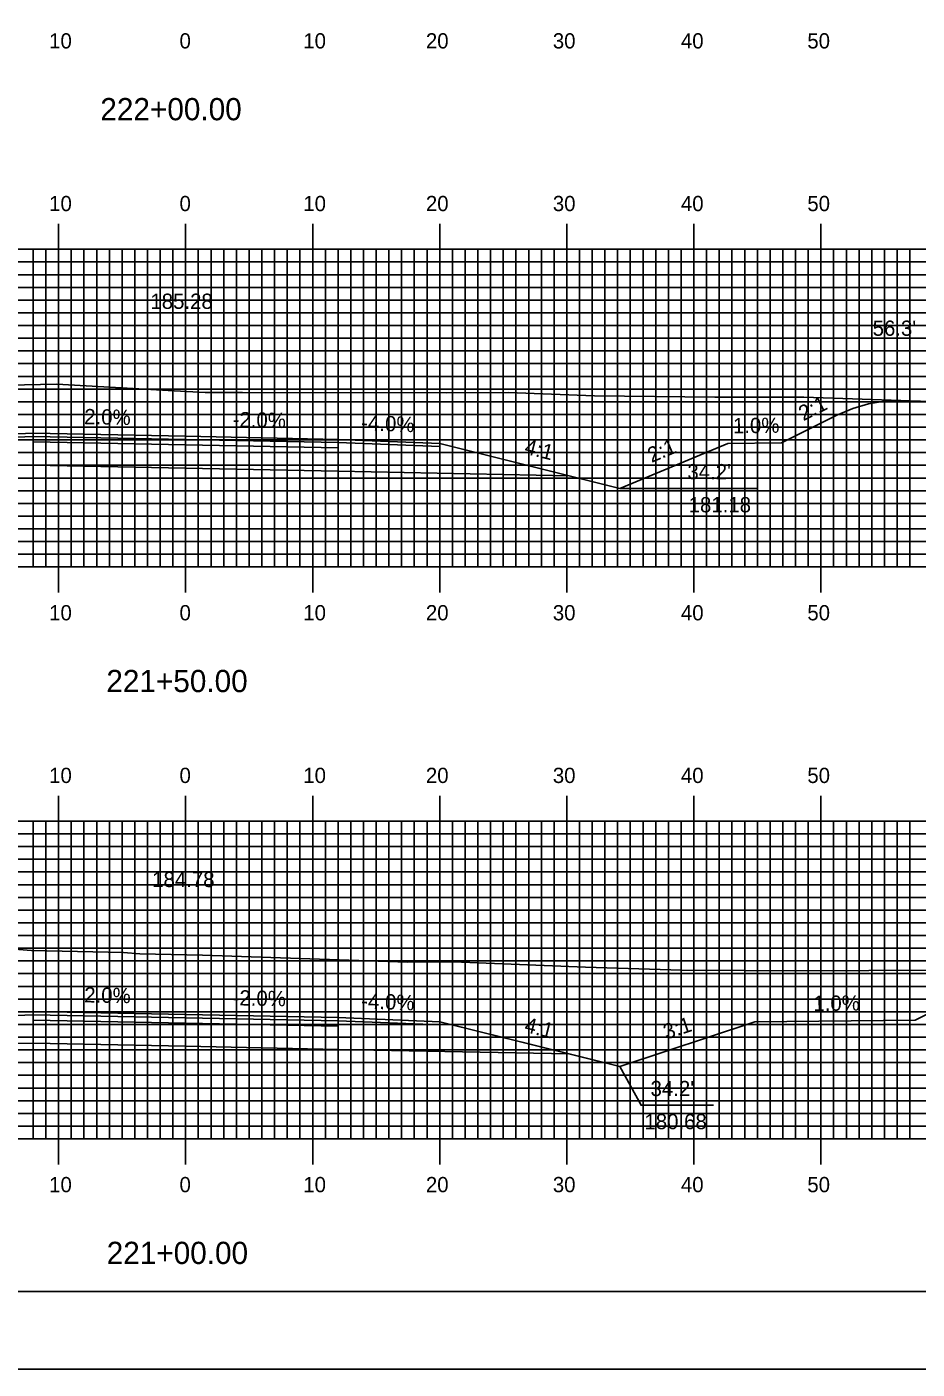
# Model space of a CAD drawing. Extents: x 1797601 to 1797944, y 442591 to 442811.
# Drawn here: x 1797753.9 to 1797824, y 442590.5 to 442696.2 of the extents above; entities that cross this region are included whole.
import ezdxf

# ---------------------------------------------------------------- set-up
doc = ezdxf.new("R2010")
doc.units = 0
for name, color, linetype in [('ANNOTATION', 7, 'Continuous'), ('BORDER', 7, 'Continuous'), ('D_Roadway_Centerline', 7, 'Continuous'), ('D_Roadway_Centerline_Text', 7, 'Continuous'), ('D_Roadway_Edge_Shoulder', 7, 'Continuous'), ('D_Roadway_Edge_TW', 7, 'Continuous'), ('D_Roadway_Pavement', 7, 'Continuous'), ('D_Roadway_SlopeLines', 7, 'Continuous'), ('D_Roadway_SubGrade', 7, 'Continuous'), ('D_Text_Standard', 7, 'Continuous'), ('H_V ANNOTATION', 7, 'Continuous'), ('MAJOR', 7, 'Continuous'), ('MINOR', 7, 'Continuous'), ('PDRAIN', 7, 'Continuous'), ('PLOT BOUNDARY', 7, 'Continuous'), ('S_Roadway_Centerline', 7, 'Continuous')]:
    doc.layers.add(name, color=color, linetype=linetype)

msp = doc.modelspace()

# ---------------------------------------------------------------- linework, layer by layer
at = {"layer": 'ANNOTATION'}
msp.add_lwpolyline([(1797807.99, 442611.31), (1797802.29, 442611.31), (1797800.62, 442614.35)], dxfattribs=at)
at = {"layer": 'BORDER'}
msp.add_lwpolyline([(1797616.84, 442596.67), (1797936.84, 442596.67), (1797936.84, 442806.67), (1797616.84, 442806.67)], close=True, dxfattribs=at)
at = {"layer": 'D_Roadway_Centerline'}
for points in [[(1797710.19, 442668.6), (1797711.44, 442668.5), (1797712.69, 442668.24), (1797713.94, 442667.84), (1797715.19, 442667.28), (1797721.99, 442663.89), (1797723.77, 442663.87), (1797732.27, 442660.33), (1797736.27, 442661.33), (1797746.44, 442663.87), (1797754.44, 442664.19), (1797766.44, 442663.95), (1797778.44, 442663.71), (1797786.44, 442663.39), (1797796.62, 442660.85), (1797800.62, 442659.85), (1797809.12, 442663.39), (1797813.34, 442663.43), (1797817.69, 442665.61), (1797818.94, 442666.15), (1797820.19, 442666.52), (1797821.44, 442666.73), (1797822.69, 442666.77)], [(1797698.94, 442623.65), (1797700.19, 442623.55), (1797701.44, 442623.31), (1797702.69, 442622.91), (1797703.94, 442622.36), (1797711.73, 442618.47), (1797721.64, 442618.37), (1797732.27, 442614.83), (1797736.27, 442615.83), (1797746.44, 442618.37), (1797754.44, 442618.69), (1797766.44, 442618.45), (1797778.44, 442618.21), (1797786.44, 442617.89), (1797796.62, 442615.35), (1797800.62, 442614.35), (1797811.25, 442617.89), (1797823.86, 442618.01), (1797828.94, 442620.56), (1797830.19, 442621.1), (1797831.44, 442621.48), (1797832.69, 442621.7), (1797833.94, 442621.75)]]:
    msp.add_lwpolyline(points, dxfattribs=at)
at = {"layer": 'D_Roadway_Edge_Shoulder'}
for points in [[(1797754.44, 442664.19), (1797746.44, 442663.87), (1797746.44, 442663.62), (1797754.44, 442663.94)], [(1797778.44, 442663.71), (1797786.44, 442663.39), (1797786.44, 442663.14), (1797778.44, 442663.46)], [(1797754.44, 442618.69), (1797746.44, 442618.37), (1797746.44, 442618.12), (1797754.44, 442618.44)], [(1797778.44, 442618.21), (1797786.44, 442617.89), (1797786.44, 442617.64), (1797778.44, 442617.96)]]:
    msp.add_lwpolyline(points, close=True, dxfattribs=at)
at = {"layer": 'D_Roadway_Edge_TW'}
for points in [[(1797754.44, 442663.94), (1797754.44, 442664.19), (1797766.44, 442663.95), (1797778.44, 442663.71), (1797778.44, 442663.46), (1797766.44, 442663.7)], [(1797754.44, 442618.44), (1797754.44, 442618.69), (1797766.44, 442618.45), (1797778.44, 442618.21), (1797778.44, 442617.96), (1797766.44, 442618.2)]]:
    msp.add_lwpolyline(points, close=True, dxfattribs=at)
at = {"layer": 'D_Roadway_Pavement'}
for points in [[(1797754.44, 442663.52), (1797754.44, 442663.94), (1797766.44, 442663.7), (1797778.44, 442663.46), (1797778.44, 442663.04), (1797766.44, 442663.28)], [(1797754.44, 442618.02), (1797754.44, 442618.44), (1797766.44, 442618.2), (1797778.44, 442617.96), (1797778.44, 442617.54), (1797766.44, 442617.78)]]:
    msp.add_lwpolyline(points, close=True, dxfattribs=at)
at = {"layer": 'D_Roadway_SlopeLines'}
for points in [[(1797809.12, 442663.39), (1797813.34, 442663.43), (1797817.69, 442665.61), (1797818.94, 442666.15), (1797820.19, 442666.52), (1797821.44, 442666.73), (1797822.69, 442666.77)], [(1797786.44, 442663.39), (1797800.62, 442659.85)], [(1797800.62, 442659.85), (1797809.12, 442663.39)], [(1797811.25, 442617.89), (1797823.86, 442618.01), (1797828.94, 442620.56), (1797830.19, 442621.1), (1797831.44, 442621.48), (1797832.69, 442621.7), (1797833.94, 442621.75)], [(1797786.44, 442617.89), (1797800.62, 442614.35)], [(1797800.62, 442614.35), (1797811.25, 442617.89)]]:
    msp.add_lwpolyline(points, dxfattribs=at)
at = {"layer": 'D_Roadway_SubGrade'}
for points in [[(1797754.44, 442661.69), (1797736.27, 442661.33), (1797746.44, 442663.87), (1797746.44, 442663.62), (1797754.44, 442663.94), (1797766.44, 442663.7), (1797778.44, 442663.46), (1797786.44, 442663.14), (1797786.44, 442663.39), (1797796.62, 442660.85), (1797778.44, 442661.21), (1797766.44, 442661.45)], [(1797754.44, 442616.19), (1797736.27, 442615.83), (1797746.44, 442618.37), (1797746.44, 442618.12), (1797754.44, 442618.44), (1797766.44, 442618.2), (1797778.44, 442617.96), (1797786.44, 442617.64), (1797786.44, 442617.89), (1797796.62, 442615.35), (1797778.44, 442615.71), (1797766.44, 442615.95)]]:
    msp.add_lwpolyline(points, close=True, dxfattribs=at)
at = {"layer": 'MAJOR'}
for p, q in [((1797756.44, 442680.67), (1797756.44, 442678.67)), ((1797766.44, 442680.67), (1797766.44, 442678.67)), ((1797776.44, 442680.67), (1797776.44, 442678.67)), ((1797786.44, 442680.67), (1797786.44, 442678.67)), ((1797796.44, 442680.67), (1797796.44, 442678.67)), ((1797806.44, 442680.67), (1797806.44, 442678.67)), ((1797816.44, 442680.67), (1797816.44, 442678.67)), ((1797626.44, 442678.67), (1797906.44, 442678.67)), ((1797626.44, 442678.67), (1797906.44, 442678.67)), ((1797756.44, 442653.67), (1797756.44, 442678.67)), ((1797766.44, 442653.67), (1797766.44, 442678.67)), ((1797776.44, 442653.67), (1797776.44, 442678.67)), ((1797786.44, 442653.67), (1797786.44, 442678.67)), ((1797796.44, 442653.67), (1797796.44, 442678.67)), ((1797806.44, 442653.67), (1797806.44, 442678.67)), ((1797816.44, 442653.67), (1797816.44, 442678.67)), ((1797626.44, 442673.67), (1797906.44, 442673.67)), ((1797626.44, 442668.67), (1797906.44, 442668.67)), ((1797626.44, 442663.67), (1797906.44, 442663.67)), ((1797626.44, 442658.67), (1797906.44, 442658.67)), ((1797626.44, 442653.67), (1797906.44, 442653.67)), ((1797626.44, 442653.67), (1797906.44, 442653.67)), ((1797756.44, 442651.66), (1797756.44, 442653.67)), ((1797766.44, 442651.66), (1797766.44, 442653.67)), ((1797776.44, 442651.66), (1797776.44, 442653.67)), ((1797786.44, 442651.66), (1797786.44, 442653.67)), ((1797796.44, 442651.66), (1797796.44, 442653.67)), ((1797806.44, 442651.66), (1797806.44, 442653.67)), ((1797816.44, 442651.66), (1797816.44, 442653.67)), ((1797756.44, 442635.67), (1797756.44, 442633.67)), ((1797766.44, 442635.67), (1797766.44, 442633.67)), ((1797776.44, 442635.67), (1797776.44, 442633.67)), ((1797786.44, 442635.67), (1797786.44, 442633.67)), ((1797796.44, 442635.67), (1797796.44, 442633.67)), ((1797806.44, 442635.67), (1797806.44, 442633.67)), ((1797816.44, 442635.67), (1797816.44, 442633.67)), ((1797626.44, 442633.67), (1797906.44, 442633.67)), ((1797626.44, 442633.67), (1797906.44, 442633.67)), ((1797756.44, 442608.67), (1797756.44, 442633.67)), ((1797766.44, 442608.67), (1797766.44, 442633.67)), ((1797776.44, 442608.67), (1797776.44, 442633.67)), ((1797786.44, 442608.67), (1797786.44, 442633.67)), ((1797796.44, 442608.67), (1797796.44, 442633.67)), ((1797806.44, 442608.67), (1797806.44, 442633.67)), ((1797816.44, 442608.67), (1797816.44, 442633.67)), ((1797626.44, 442628.67), (1797906.44, 442628.67)), ((1797626.44, 442623.67), (1797906.44, 442623.67)), ((1797626.44, 442618.67), (1797906.44, 442618.67)), ((1797626.44, 442613.67), (1797906.44, 442613.67)), ((1797626.44, 442608.67), (1797906.44, 442608.67)), ((1797626.44, 442608.67), (1797906.44, 442608.67)), ((1797756.44, 442606.66), (1797756.44, 442608.67)), ((1797766.44, 442606.66), (1797766.44, 442608.67)), ((1797776.44, 442606.66), (1797776.44, 442608.67)), ((1797786.44, 442606.66), (1797786.44, 442608.67)), ((1797796.44, 442606.66), (1797796.44, 442608.67)), ((1797806.44, 442606.66), (1797806.44, 442608.67)), ((1797816.44, 442606.66), (1797816.44, 442608.67))]:
    msp.add_line(p, q, dxfattribs=at)
at = {"layer": 'MINOR'}
for p, q in [((1797754.44, 442653.67), (1797754.44, 442678.67)), ((1797755.44, 442653.67), (1797755.44, 442678.67)), ((1797757.44, 442653.67), (1797757.44, 442678.67)), ((1797758.44, 442653.67), (1797758.44, 442678.67)), ((1797759.44, 442653.67), (1797759.44, 442678.67)), ((1797760.44, 442653.67), (1797760.44, 442678.67)), ((1797761.44, 442653.67), (1797761.44, 442678.67)), ((1797762.44, 442653.67), (1797762.44, 442678.67)), ((1797763.44, 442653.67), (1797763.44, 442678.67)), ((1797764.44, 442653.67), (1797764.44, 442678.67)), ((1797765.44, 442653.67), (1797765.44, 442678.67)), ((1797767.44, 442653.67), (1797767.44, 442678.67)), ((1797768.44, 442653.67), (1797768.44, 442678.67)), ((1797769.44, 442653.67), (1797769.44, 442678.67)), ((1797770.44, 442653.67), (1797770.44, 442678.67)), ((1797771.44, 442653.67), (1797771.44, 442678.67)), ((1797772.44, 442653.67), (1797772.44, 442678.67)), ((1797773.44, 442653.67), (1797773.44, 442678.67)), ((1797774.44, 442653.67), (1797774.44, 442678.67)), ((1797775.44, 442653.67), (1797775.44, 442678.67)), ((1797777.44, 442653.67), (1797777.44, 442678.67)), ((1797778.44, 442653.67), (1797778.44, 442678.67)), ((1797779.44, 442653.67), (1797779.44, 442678.67)), ((1797780.44, 442653.67), (1797780.44, 442678.67)), ((1797781.44, 442653.67), (1797781.44, 442678.67)), ((1797782.44, 442653.67), (1797782.44, 442678.67)), ((1797783.44, 442653.67), (1797783.44, 442678.67)), ((1797784.44, 442653.67), (1797784.44, 442678.67)), ((1797785.44, 442653.67), (1797785.44, 442678.67)), ((1797787.44, 442653.67), (1797787.44, 442678.67)), ((1797788.44, 442653.67), (1797788.44, 442678.67)), ((1797789.44, 442653.67), (1797789.44, 442678.67)), ((1797790.44, 442653.67), (1797790.44, 442678.67)), ((1797791.44, 442653.67), (1797791.44, 442678.67)), ((1797792.44, 442653.67), (1797792.44, 442678.67)), ((1797793.44, 442653.67), (1797793.44, 442678.67)), ((1797794.44, 442653.67), (1797794.44, 442678.67)), ((1797795.44, 442653.67), (1797795.44, 442678.67)), ((1797797.44, 442653.67), (1797797.44, 442678.67)), ((1797798.44, 442653.67), (1797798.44, 442678.67)), ((1797799.44, 442653.67), (1797799.44, 442678.67)), ((1797800.44, 442653.67), (1797800.44, 442678.67)), ((1797801.44, 442653.67), (1797801.44, 442678.67)), ((1797802.44, 442653.67), (1797802.44, 442678.67)), ((1797803.44, 442653.67), (1797803.44, 442678.67)), ((1797804.44, 442653.67), (1797804.44, 442678.67)), ((1797805.44, 442653.67), (1797805.44, 442678.67)), ((1797807.44, 442653.67), (1797807.44, 442678.67)), ((1797808.44, 442653.67), (1797808.44, 442678.67)), ((1797809.44, 442653.67), (1797809.44, 442678.67)), ((1797810.44, 442653.67), (1797810.44, 442678.67)), ((1797811.44, 442653.67), (1797811.44, 442678.67)), ((1797812.44, 442653.67), (1797812.44, 442678.67)), ((1797813.44, 442653.67), (1797813.44, 442678.67)), ((1797814.44, 442653.67), (1797814.44, 442678.67)), ((1797815.44, 442653.67), (1797815.44, 442678.67)), ((1797817.44, 442653.67), (1797817.44, 442678.67)), ((1797818.44, 442653.67), (1797818.44, 442678.67)), ((1797819.44, 442653.67), (1797819.44, 442678.67)), ((1797820.44, 442653.67), (1797820.44, 442678.67)), ((1797821.44, 442653.67), (1797821.44, 442678.67)), ((1797822.44, 442653.67), (1797822.44, 442678.67)), ((1797823.44, 442653.67), (1797823.44, 442678.67)), ((1797626.44, 442677.67), (1797906.44, 442677.67)), ((1797626.44, 442676.67), (1797906.44, 442676.67)), ((1797626.44, 442675.67), (1797906.44, 442675.67)), ((1797626.44, 442674.67), (1797906.44, 442674.67)), ((1797626.44, 442672.67), (1797906.44, 442672.67)), ((1797626.44, 442671.67), (1797906.44, 442671.67)), ((1797626.44, 442670.67), (1797906.44, 442670.67)), ((1797626.44, 442669.67), (1797906.44, 442669.67)), ((1797626.44, 442667.67), (1797906.44, 442667.67)), ((1797626.44, 442666.67), (1797906.44, 442666.67)), ((1797626.44, 442665.67), (1797906.44, 442665.67)), ((1797626.44, 442664.67), (1797906.44, 442664.67)), ((1797626.44, 442662.67), (1797906.44, 442662.67)), ((1797626.44, 442661.67), (1797906.44, 442661.67)), ((1797626.44, 442660.67), (1797906.44, 442660.67)), ((1797626.44, 442659.67), (1797906.44, 442659.67)), ((1797626.44, 442657.67), (1797906.44, 442657.67)), ((1797626.44, 442656.67), (1797906.44, 442656.67)), ((1797626.44, 442655.67), (1797906.44, 442655.67)), ((1797626.44, 442654.67), (1797906.44, 442654.67)), ((1797754.44, 442608.67), (1797754.44, 442633.67)), ((1797755.44, 442608.67), (1797755.44, 442633.67)), ((1797757.44, 442608.67), (1797757.44, 442633.67)), ((1797758.44, 442608.67), (1797758.44, 442633.67)), ((1797759.44, 442608.67), (1797759.44, 442633.67)), ((1797760.44, 442608.67), (1797760.44, 442633.67)), ((1797761.44, 442608.67), (1797761.44, 442633.67)), ((1797762.44, 442608.67), (1797762.44, 442633.67)), ((1797763.44, 442608.67), (1797763.44, 442633.67)), ((1797764.44, 442608.67), (1797764.44, 442633.67)), ((1797765.44, 442608.67), (1797765.44, 442633.67)), ((1797767.44, 442608.67), (1797767.44, 442633.67)), ((1797768.44, 442608.67), (1797768.44, 442633.67)), ((1797769.44, 442608.67), (1797769.44, 442633.67)), ((1797770.44, 442608.67), (1797770.44, 442633.67)), ((1797771.44, 442608.67), (1797771.44, 442633.67)), ((1797772.44, 442608.67), (1797772.44, 442633.67)), ((1797773.44, 442608.67), (1797773.44, 442633.67)), ((1797774.44, 442608.67), (1797774.44, 442633.67)), ((1797775.44, 442608.67), (1797775.44, 442633.67)), ((1797777.44, 442608.67), (1797777.44, 442633.67)), ((1797778.44, 442608.67), (1797778.44, 442633.67)), ((1797779.44, 442608.67), (1797779.44, 442633.67)), ((1797780.44, 442608.67), (1797780.44, 442633.67)), ((1797781.44, 442608.67), (1797781.44, 442633.67)), ((1797782.44, 442608.67), (1797782.44, 442633.67)), ((1797783.44, 442608.67), (1797783.44, 442633.67)), ((1797784.44, 442608.67), (1797784.44, 442633.67)), ((1797785.44, 442608.67), (1797785.44, 442633.67)), ((1797787.44, 442608.67), (1797787.44, 442633.67)), ((1797788.44, 442608.67), (1797788.44, 442633.67)), ((1797789.44, 442608.67), (1797789.44, 442633.67)), ((1797790.44, 442608.67), (1797790.44, 442633.67)), ((1797791.44, 442608.67), (1797791.44, 442633.67)), ((1797792.44, 442608.67), (1797792.44, 442633.67)), ((1797793.44, 442608.67), (1797793.44, 442633.67)), ((1797794.44, 442608.67), (1797794.44, 442633.67)), ((1797795.44, 442608.67), (1797795.44, 442633.67)), ((1797797.44, 442608.67), (1797797.44, 442633.67)), ((1797798.44, 442608.67), (1797798.44, 442633.67)), ((1797799.44, 442608.67), (1797799.44, 442633.67)), ((1797800.44, 442608.67), (1797800.44, 442633.67)), ((1797801.44, 442608.67), (1797801.44, 442633.67)), ((1797802.44, 442608.67), (1797802.44, 442633.67)), ((1797803.44, 442608.67), (1797803.44, 442633.67)), ((1797804.44, 442608.67), (1797804.44, 442633.67)), ((1797805.44, 442608.67), (1797805.44, 442633.67)), ((1797807.44, 442608.67), (1797807.44, 442633.67)), ((1797808.44, 442608.67), (1797808.44, 442633.67)), ((1797809.44, 442608.67), (1797809.44, 442633.67)), ((1797810.44, 442608.67), (1797810.44, 442633.67)), ((1797811.44, 442608.67), (1797811.44, 442633.67)), ((1797812.44, 442608.67), (1797812.44, 442633.67)), ((1797813.44, 442608.67), (1797813.44, 442633.67)), ((1797814.44, 442608.67), (1797814.44, 442633.67)), ((1797815.44, 442608.67), (1797815.44, 442633.67)), ((1797817.44, 442608.67), (1797817.44, 442633.67)), ((1797818.44, 442608.67), (1797818.44, 442633.67)), ((1797819.44, 442608.67), (1797819.44, 442633.67)), ((1797820.44, 442608.67), (1797820.44, 442633.67)), ((1797821.44, 442608.67), (1797821.44, 442633.67)), ((1797822.44, 442608.67), (1797822.44, 442633.67)), ((1797823.44, 442608.67), (1797823.44, 442633.67)), ((1797626.44, 442632.67), (1797906.44, 442632.67)), ((1797626.44, 442631.67), (1797906.44, 442631.67)), ((1797626.44, 442630.67), (1797906.44, 442630.67)), ((1797626.44, 442629.67), (1797906.44, 442629.67)), ((1797626.44, 442627.67), (1797906.44, 442627.67)), ((1797626.44, 442626.67), (1797906.44, 442626.67)), ((1797626.44, 442625.67), (1797906.44, 442625.67)), ((1797626.44, 442624.67), (1797906.44, 442624.67)), ((1797626.44, 442622.67), (1797906.44, 442622.67)), ((1797626.44, 442621.67), (1797906.44, 442621.67)), ((1797626.44, 442620.67), (1797906.44, 442620.67)), ((1797626.44, 442619.67), (1797906.44, 442619.67)), ((1797626.44, 442617.67), (1797906.44, 442617.67)), ((1797626.44, 442616.67), (1797906.44, 442616.67)), ((1797626.44, 442615.67), (1797906.44, 442615.67)), ((1797626.44, 442614.67), (1797906.44, 442614.67)), ((1797626.44, 442612.67), (1797906.44, 442612.67)), ((1797626.44, 442611.67), (1797906.44, 442611.67)), ((1797626.44, 442610.67), (1797906.44, 442610.67)), ((1797626.44, 442609.67), (1797906.44, 442609.67))]:
    msp.add_line(p, q, dxfattribs=at)
at = {"layer": 'PDRAIN'}
msp.add_line((1797800.62, 442659.85), (1797811.39, 442659.85), dxfattribs=at)
at = {"layer": 'PLOT BOUNDARY'}
msp.add_lwpolyline([(1797600.66, 442590.55), (1797940.66, 442590.55), (1797940.66, 442810.55), (1797600.66, 442810.55)], close=True, dxfattribs=at)
at = {"layer": 'S_Roadway_Centerline'}
for points in [[(1797692.6, 442668.6), (1797703.82, 442668.64), (1797710.4, 442668.6), (1797719.38, 442668.33), (1797724.97, 442668.13), (1797742.03, 442667.89), (1797745.51, 442667.83), (1797746.07, 442667.84), (1797756.3, 442668.06), (1797765.54, 442667.52), (1797767.98, 442667.4), (1797770.93, 442667.39), (1797787, 442667.37), (1797791.84, 442667.4), (1797798.61, 442667.13), (1797808.08, 442667.03), (1797815.1, 442667.03), (1797826.56, 442666.64)], [(1797692.59, 442623.76), (1797701.04, 442623.61), (1797708.19, 442623.68), (1797721.04, 442623.87), (1797726.49, 442623.62), (1797733.52, 442624.15), (1797739.54, 442624.14), (1797742.04, 442624.15), (1797746.65, 442624.1), (1797754.31, 442623.48), (1797761.56, 442623.32), (1797762.84, 442623.24), (1797767.77, 442623.12), (1797783.91, 442622.58), (1797785.81, 442622.61), (1797788.16, 442622.56), (1797797.92, 442622.17), (1797805.46, 442621.94), (1797815.49, 442621.88), (1797824.93, 442621.95)]]:
    msp.add_lwpolyline(points, dxfattribs=at)

# ---------------------------------------------------------------- texts
at = {"layer": 'ANNOTATION'}
for s, rotation, p in [('2:1', 26.5651, (1797815.06, 442665.13)), ('2.0%', 358.8542, (1797758.45, 442664.91)), ('-2.0%', 358.8542, (1797770.13, 442664.68)), ('-4.0%', 357.7094, (1797780.24, 442664.44)), ('1.0%', 0.5729, (1797809.52, 442664.19)), ('4:1', 345.9638, (1797793.04, 442662.6)), ('2:1', 22.6199, (1797803.11, 442661.85)), ('2.0%', 358.8542, (1797758.45, 442619.41)), ('-2.0%', 358.8542, (1797770.13, 442619.18)), ('-4.0%', 357.7094, (1797780.24, 442618.94)), ('1.0%', 0.5729, (1797815.85, 442618.73)), ('4:1', 345.9638, (1797793.04, 442617.1)), ('3:1', 18.435, (1797804.27, 442616.47))]:
    msp.add_text(s, height=1.2, rotation=rotation, dxfattribs=at).set_placement(p)
for s, p in [("34.2'", (1797805.93, 442660.57)), ('181.18', (1797806.03, 442657.97)), ("34.2'", (1797803.03, 442612.03)), ('180.68', (1797802.55, 442609.43))]:
    msp.add_text(s, height=1.2, dxfattribs=at).set_placement(p)
at = {"layer": 'D_Roadway_Centerline'}
for s, p in [('C', (1797766.44, 442663.95)), ('L', (1797766.44, 442663.94)), ('C', (1797766.44, 442618.45)), ('L', (1797766.44, 442618.44))]:
    msp.add_text(s, height=0.0146, dxfattribs=at).set_placement(p)
at = {"layer": 'D_Roadway_Centerline_Text'}
for s, p in [('185.28', (1797763.67, 442673.98)), ('184.78', (1797763.81, 442628.48))]:
    msp.add_text(s, height=1.2, dxfattribs=at).set_placement(p)
at = {"layer": 'D_Text_Standard'}
msp.add_text("56.3'", height=1.2, dxfattribs=at).set_placement((1797820.51, 442671.86))
at = {"layer": 'H_V ANNOTATION'}
for s, height, p in [('10', 1.2, (1797755.7, 442694.47)), ('0', 1.2, (1797765.96, 442694.47)), ('10', 1.2, (1797775.7, 442694.47)), ('20', 1.2, (1797785.35, 442694.47)), ('30', 1.2, (1797795.34, 442694.47)), ('40', 1.2, (1797805.42, 442694.47)), ('50', 1.2, (1797815.37, 442694.47)), ('222+00.00', 1.75, (1797759.73, 442688.82)), ('10', 1.2, (1797755.7, 442681.67)), ('0', 1.2, (1797765.96, 442681.67)), ('10', 1.2, (1797775.7, 442681.67)), ('20', 1.2, (1797785.35, 442681.67)), ('30', 1.2, (1797795.34, 442681.67)), ('40', 1.2, (1797805.42, 442681.67)), ('50', 1.2, (1797815.37, 442681.67)), ('10', 1.2, (1797755.7, 442649.47)), ('0', 1.2, (1797765.96, 442649.47)), ('10', 1.2, (1797775.7, 442649.47)), ('20', 1.2, (1797785.35, 442649.47)), ('30', 1.2, (1797795.34, 442649.47)), ('40', 1.2, (1797805.42, 442649.47)), ('50', 1.2, (1797815.37, 442649.47)), ('221+50.00', 1.75, (1797760.2, 442643.82)), ('10', 1.2, (1797755.7, 442636.67)), ('0', 1.2, (1797765.96, 442636.67)), ('10', 1.2, (1797775.7, 442636.67)), ('20', 1.2, (1797785.35, 442636.67)), ('30', 1.2, (1797795.34, 442636.67)), ('40', 1.2, (1797805.42, 442636.67)), ('50', 1.2, (1797815.37, 442636.67)), ('10', 1.2, (1797755.7, 442604.47)), ('0', 1.2, (1797765.96, 442604.47)), ('10', 1.2, (1797775.7, 442604.47)), ('20', 1.2, (1797785.35, 442604.47)), ('30', 1.2, (1797795.34, 442604.47)), ('40', 1.2, (1797805.42, 442604.47)), ('50', 1.2, (1797815.37, 442604.47)), ('221+00.00', 1.75, (1797760.23, 442598.82))]:
    msp.add_text(s, height=height, dxfattribs=at).set_placement(p)

doc.saveas('drawing.dxf')
